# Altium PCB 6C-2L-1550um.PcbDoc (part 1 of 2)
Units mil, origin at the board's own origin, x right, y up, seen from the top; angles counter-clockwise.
Board outline 3937.01 x 2952.76 mil, 2 copper layers (Top Layer, Bottom Layer), stack 62.442 mil thick; 172 components, 97 nets, 523 pads, 239 vias.
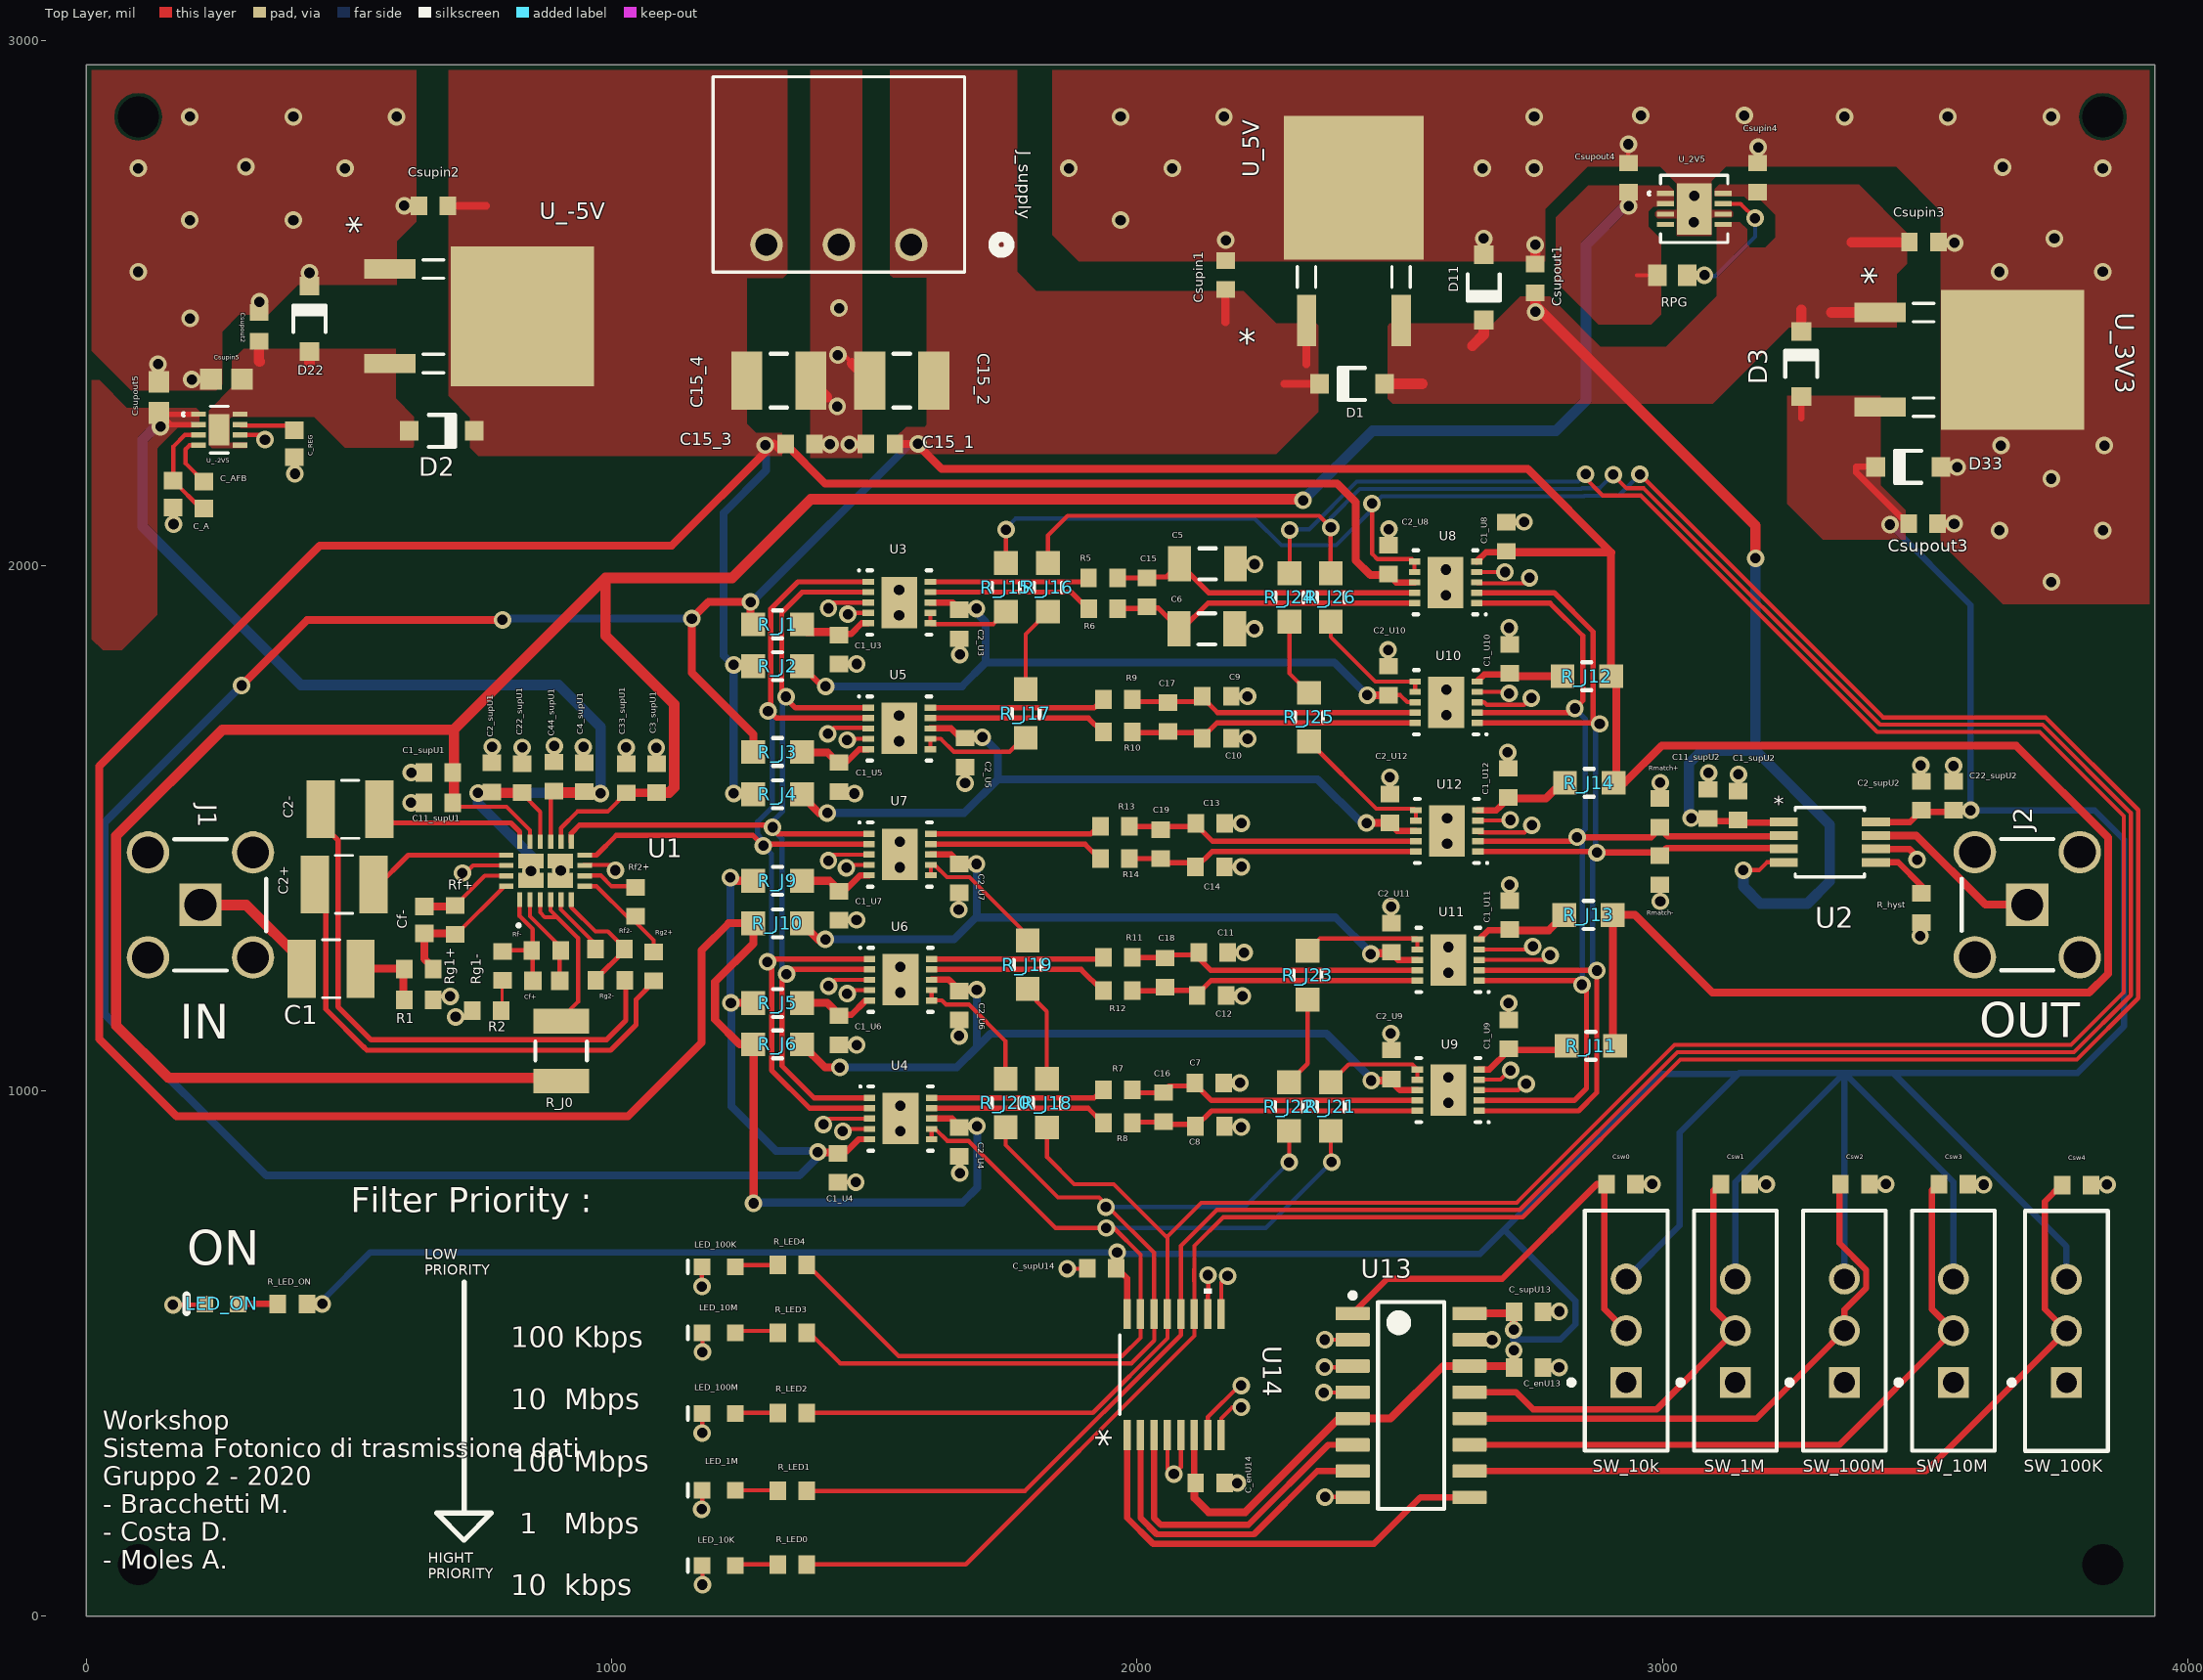
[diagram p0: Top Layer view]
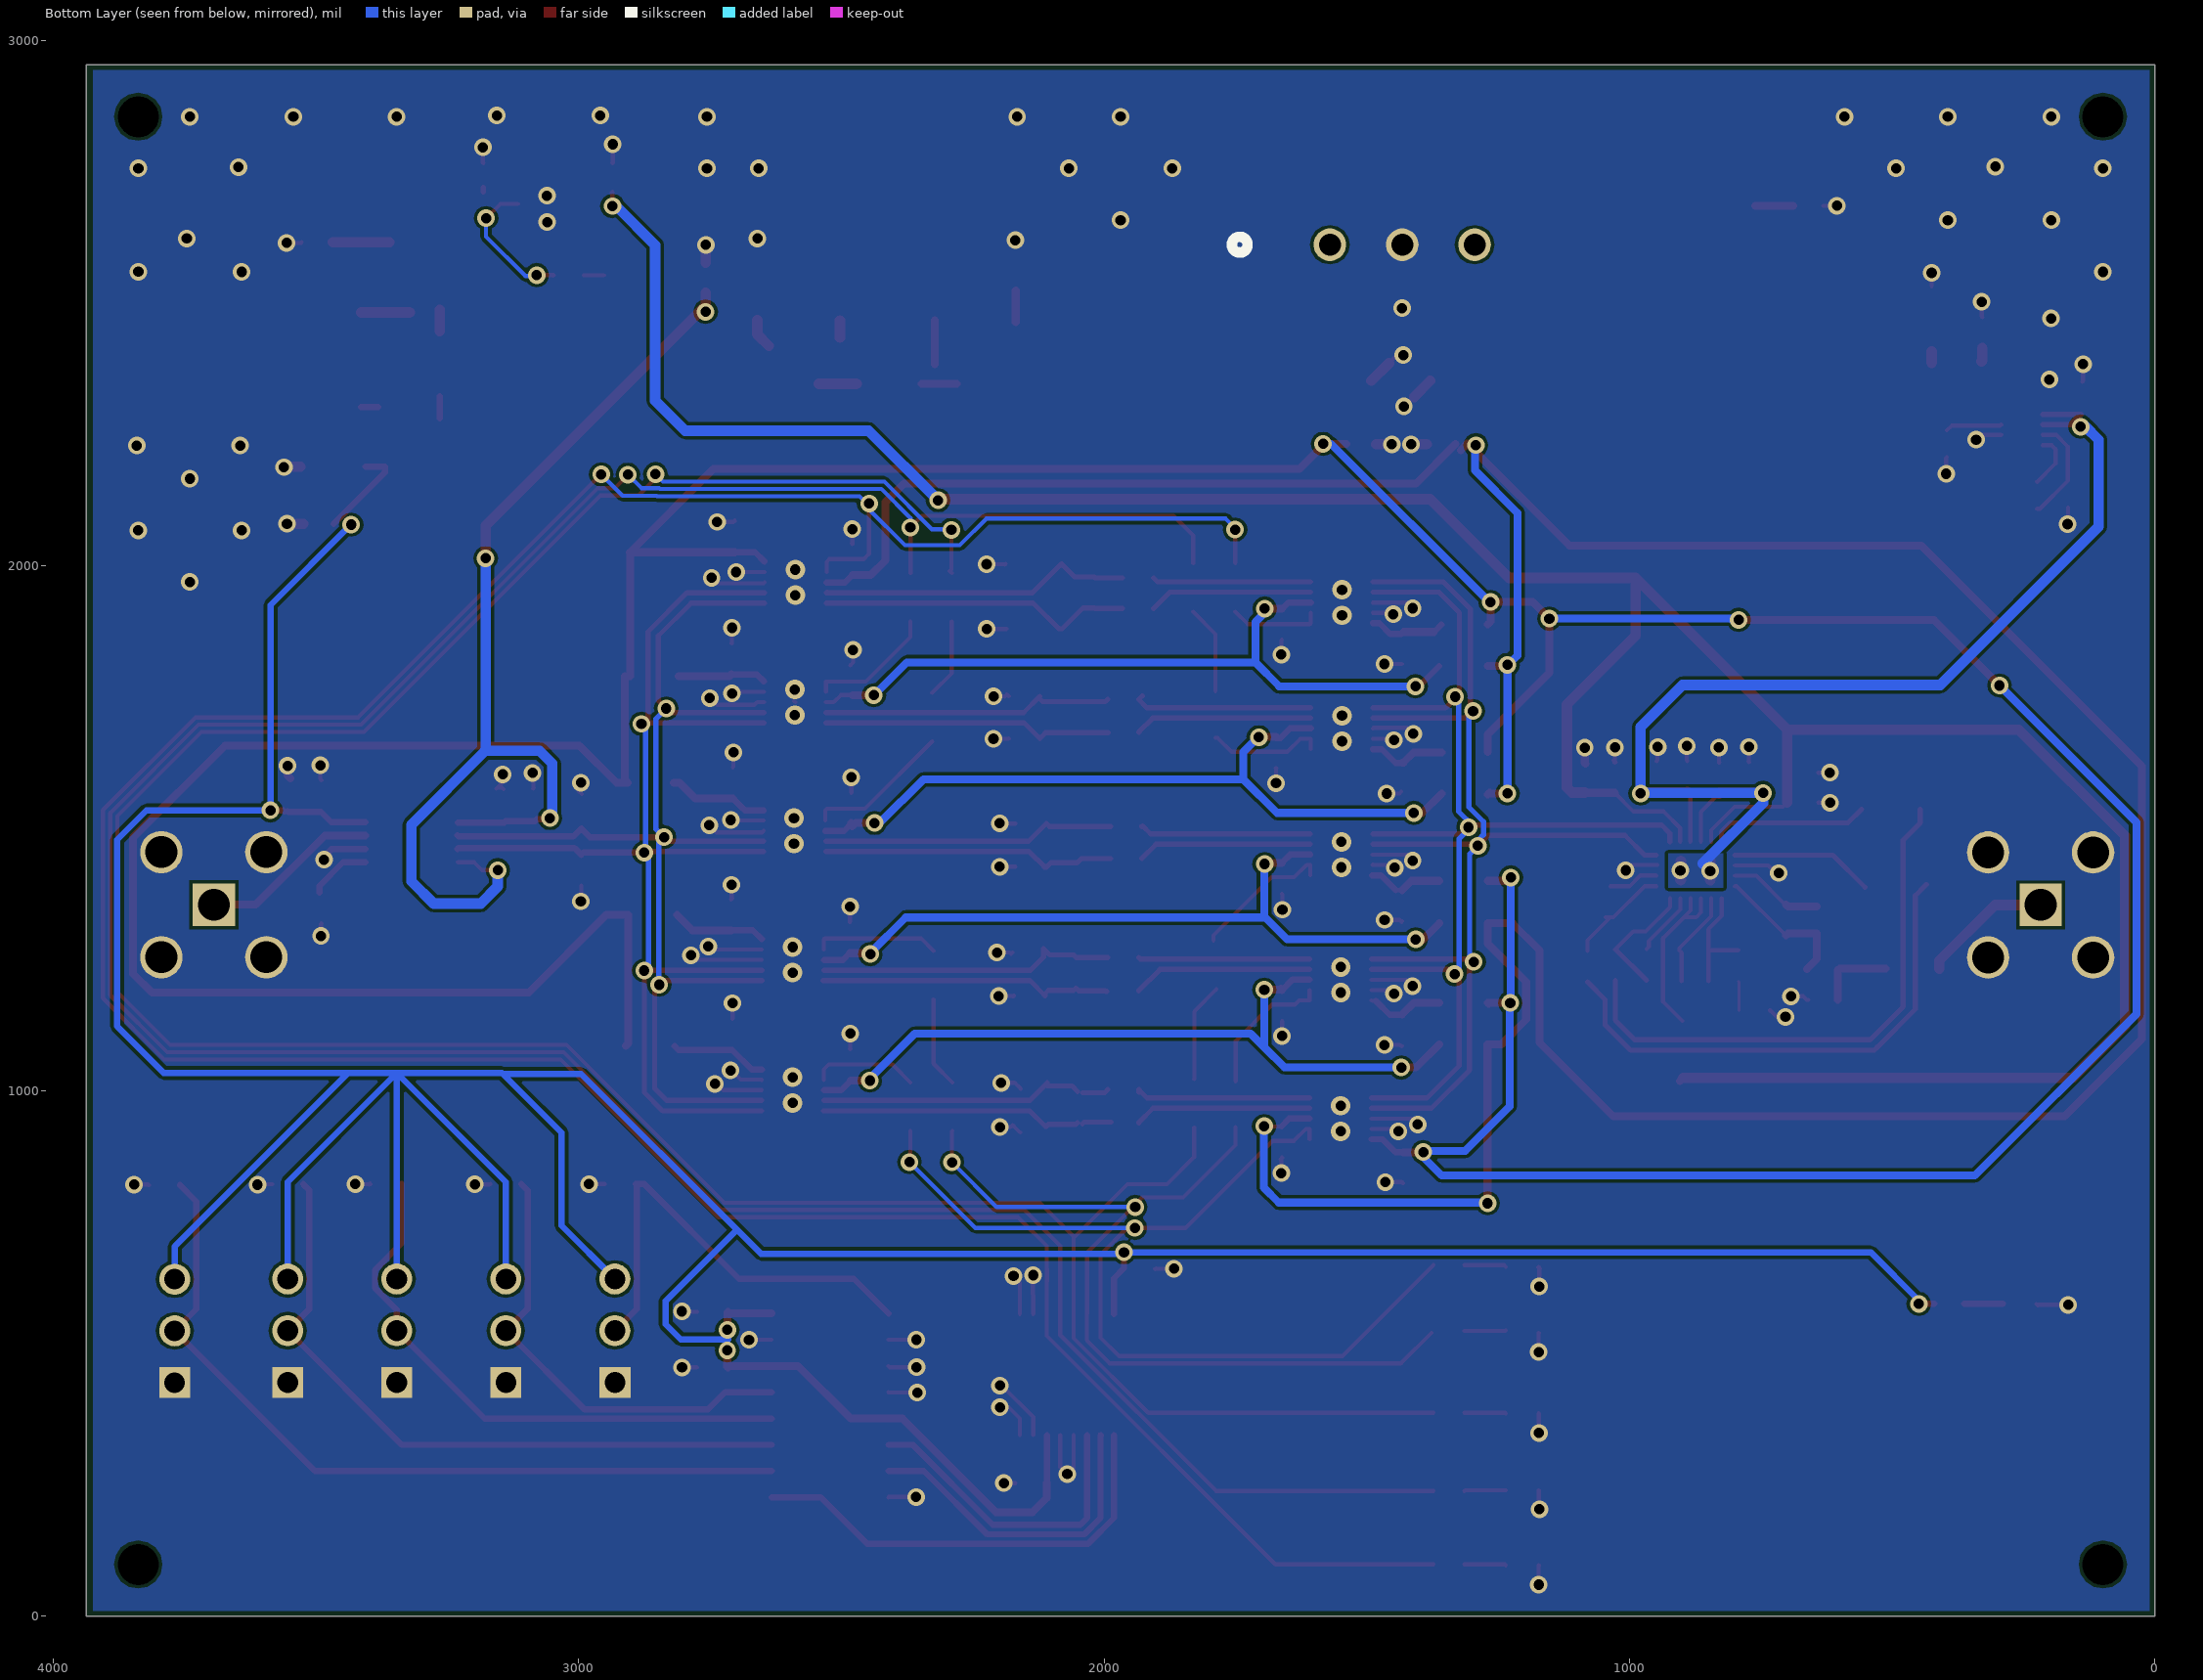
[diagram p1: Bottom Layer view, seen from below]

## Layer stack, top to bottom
Top Solder: solder mask 0.4, Solder Resist, Dk 3.5
Top Layer: signal copper 0.709
Dielectric1: core 61.024, FR-4, Dk 4.8
Bottom Layer: signal copper 0.709
Bottom Solder: solder mask 0.4, Solder Resist, Dk 3.5

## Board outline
3937.01,2952.76 0,2952.76 0,0 3937.01,0

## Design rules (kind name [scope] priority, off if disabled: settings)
BoardOutlineClearance [All] p1: gap=9.84 ignorepadtopadclearanceinfootprint=FALSE except(0: Arc-SplitContinuation Track-SplitContinuation SMDPad-SplitContinuation THPad-SplitContinuation Via-SplitContinuation Fill-SplitContinuation Poly-SplitContinuation Region-SplitContinuation Text-SplitContinuation)
Clearance Clearance-xPP-xTP-xTT [All] p1: gap=5.91 ignorepadtopadclearanceinfootprint=FALSE except(0: Arc-Hole Track-Hole SMDPad-Hole THPad-Hole Via-Hole Fill-Hole Poly-Hole Region-Hole Text-Hole)
ComponentClearance [All] p1: gap=9.84 collisioncheckmode=3 verticalgap=9.84 showdistances=FALSE
DiffPairsRouting [All] p1: maxlimit=9.84 minlimit=9.84 mostfreqgap=9.84 toplayer_minwidth=9.84 toplayer_maxwidth=15 toplayer_prefwidth=9.84 bottomlayer_minwidth=9.84 bottomlayer_maxwidth=15 bottomlayer_prefwidth=9.84 maxuncoupledlength=492.13
Height [All] p1: minheight=0 maxheight=984.25 prefheight=492.13
HoleSize HoleSize-PTH [All] p1: absolutevalues=TRUE maxlimit=78.74 minlimit=9.84 maxpercent=80.000 minpercent=20.000
HoleToHoleClearance [All] p1: gap=13.78 allowstackedmicrovias=TRUE
MinimumAnnularRing "Minimum IAR  >0.45mm" [((ObjectKind = 'Pad') OR (ObjectKind = 'Via')) And (Layer = 'MultiLayer') And (HoleDiameter > AsMM(0.45))] p1: minimumring=6.89 // minimum inner annular ring for pads > 0.45mm finished hole size
MinimumAnnularRing "Minimum IAR <=0.45mm" [((ObjectKind = 'Pad') OR (ObjectKind = 'Via')) And (Layer = 'MultiLayer') And (HoleDiameter <= AsMM(0.45))] p2: minimumring=6.89 // minimum inner annular ring for pads <= 0.45mm finished hole size
MinimumSolderMaskSliver [All] p1: minsoldermaskwidth=3.15
PlaneClearance PlaneClearance-IPI [All] p1: clearance=9.84
PlaneConnect [All] p1: planeconnectstyle=Direct reliefexpansion=6.89 reliefentries=4 reliefconductorwidth=7.87 reliefairgap=7.87
PolygonConnect PolygonConnect-xTW [All] p1: connectstyle=Direct reliefconductorwidth=7.87 reliefentries=4 polygonreliefangle="90 Angle" airgapwidth=7.87
RoutingCorners [All] p1: cornerstyle=45-Degree minsetback=98.43 maxsetback=98.43
RoutingVias "RoutingVias > 0.45mm" [(ObjectKind = 'Via') And (HoleDiameter > AsMM(0.45))] p1: holewidth=19.68 width=33.46 viastyle="Through Hole" minholewidth=19.68 minwidth=33.46 maxholewidth=35.43 maxwidth=49.21 // finishet hole size > 0.45mm
RoutingVias "RoutingVias <= 0.45mm" [(ObjectKind = 'Via') And (HoleDiameter <= AsMM(0.45))] p2: holewidth=11.81 width=25.59 viastyle="Through Hole" minholewidth=9.84 minwidth=23.62 maxholewidth=17.72 maxwidth=31.5 // finishet hole size <= 0.45mm
SilkToSilkClearance [All] p1: silktosilkclearance=7.87
SilkToSolderMaskClearance SilkscreenOverComponentPads [IsPad] p1: minsilkscreentomaskgap=7.87 clearancetoexposedcopper=TRUE
SolderMaskExpansion [All] p1: expansion=0 istentingtop=FALSE
UnRoutedNet [All] p1: checkbadconnections=TRUE
UnpouredPolygon [All] p1: allowunpoured=TRUE allowshelved=TRUE
Width Width-xTW [All] p1: maxlimit=59.06 minlimit=5.91 preferedwidth=7.87
17 further rules are at their usual default settings.

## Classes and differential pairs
component class SWITCH_stage: C1_U3 C1_U4 C1_U5 C1_U6 C1_U7 C1_U8 C1_U9 C1_U10 C1_U11 C1_U12 C2_U3 C2_U4 C2_U5 C2_U6 C2_U7 C2_U8 C2_U9 C2_U10 C2_U11 C2_U12 R_J1 R_J2 R_J3 R_J4 R_J5 R_J6 R_J9 R_J10 R_J11 R_J12 R_J13 R_J14 R_J15 R_J16 R_J17 R_J18 R_J19 R_J20 R_J21 R_J22 R_J23 R_J24 R_J25 R_J26 Rmatch+ Rmatch- U3 U4 U5 U6 U7 U8 U9 U10 U11 U12
net class 3.3V: 3V3
net class -15V: -15V
net class -5V: -5V
net class +15V: +15V
net class +5V: +5V
component class SUPPLY_15V: C15_1 C15_2 C15_3 C15_4 J_supply
component class SUPPLY_5V: C_A C_AFB C_REG Csupin1 Csupin2 Csupin4 Csupin5 Csupout1 Csupout2 Csupout4 Csupout5 D1 D2 D11 D22 RPG U_2V5 U_5V U_-2V5 U_-5V
component class SUPPLY_3V3: Csupin3 Csupout3 D3 D33 U_3V3
component class "STAGE _1_2": C1 C1_supU1 C2+ C2- C2_supU1 C3_supU1 C4_supU1 C11_supU1 C22_supU1 C33_supU1 C44_supU1 Cf+ Cf- J1 R1 R2 R_J0 Rf2+ Rf2- Rf+ Rf- Rg1+ Rg1- Rg2+ Rg2- U1
component class OUT_STAGE: C1_supU2 C2_supU2 C11_supU2 C22_supU2 J2 R_hyst U2
component class Selector_stage: C_enU13 C_enU14 C_supU13 C_supU14 Csw0 Csw1 Csw2 Csw3 Csw4 LED_1M LED_10K LED_10M LED_100K LED_100M LED_ON R_LED0 R_LED1 R_LED2 R_LED3 R_LED4 R_LED_ON SW_1M SW_10k SW_10M SW_100K SW_100M U13 U14
component class Filters: C5 C6 C7 C8 C9 C10 C11 C12 C13 C14 C15 C16 C17 C18 C19 R5 R6 R7 R8 R9 R10 R11 R12 R13 R14
differential pair Diff_Pair9: +Diff_Pair9_P -Diff_Pair9_N
differential pair Diff_pair00: +Diff_pair00_P -Diff_pair00_N
differential pair Diff_pair0: +Diff_pair0_P -Diff_pair0_N
differential pair Diff_pair61: +Diff_pair61_P -Diff_pair61_N
differential pair Diff_pair51: +Diff_pair51_P -Diff_pair51_N
differential pair Diff_pair41: +Diff_pair41_P -Diff_pair41_N
differential pair Diff_pair31: +Diff_pair31_P -Diff_pair31_N
differential pair Diff_pair21: +Diff_pair21_P -Diff_pair21_N
differential pair Diff_pair6: +Diff_pair6_P -Diff_pair6_N
differential pair Diff_pair5: +Diff_pair5_P -Diff_pair5_N
differential pair Diff_pair4: +Diff_pair4_P -Diff_pair4_N
differential pair Diff_pair3: +Diff_pair3_P -Diff_pair3_N
differential pair Diff_pair2: +Diff_pair2_P -Diff_pair2_N
differential pair Diff_pair1: +Diff_pair1_P -Diff_pair1_N

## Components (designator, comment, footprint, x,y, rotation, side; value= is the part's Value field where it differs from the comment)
C1 "JMK325ABJ337MM-PE" CAPC3225X280N 465.8,1232.54 r0 top
C1_supU1 "06031C104KAT2A" 1608[0603] 669.72,1605.77 r180 top value=100nF
C1_supU2 "06031C104KAT2A" 1608[0603] 3143.85,1543.41 r270 top value=100nF
C1_U3 "06031C104KAT2A" 1608[0603] 1432.77,1840.09 r90 top value=100nF
C1_U4 "06031C104KAT2A" 1608[0603] 1430.8,853.63 r90 top value=100nF
C1_U5 "06031C104KAT2A" 1608[0603] 1432.62,1597.42 r90 top value=100nF
C1_U6 "06031C104KAT2A" 1608[0603] 1432.77,1115.43 r90 top value=100nF
C1_U7 "06031C104KAT2A" 1608[0603] 1432.62,1352.63 r90 top value=100nF
C1_U8 "06031C104KAT2A" 1608[0603] 2703.02,2054.6 r270 top value=100nF
C1_U9 "06031C104KAT2A" 1608[0603] 2707.71,1107.55 r270 top value=100nF
C1_U10 "06031C104KAT2A" 1608[0603] 2709.06,1822.29 r270 top value=100nF
C1_U11 "06031C104KAT2A" 1608[0603] 2709.68,1334.9 r270 top value=100nF
C1_U12 "06031C104KAT2A" 1608[0603] 2706.6,1586.35 r270 top value=100nF
C2+ "JMK325ABJ337MM-PE" CAPC3225X280N 490.39,1392.88 r180 top
C2- "JMK325ABJ337MM-PE" CAPC3225X280N 501.98,1536.13 r180 top
C2_supU1 "06031C104KAT2A" 1608[0603] 772.03,1596.66 r90 top value=100nF
C2_supU2 "06031C104KAT2A" 1608[0603] 3493.12,1561.63 r270 top value=100nF
C2_U3 "06031C104KAT2A" 1608[0603] 1661.12,1888.09 r90 top value=100nF
C2_U4 "06031C104KAT2A" 1608[0603] 1661.53,902.64 r90 top value=100nF
C2_U5 "06031C104KAT2A" 1608[0603] 1672.21,1644.07 r90 top value=100nF
C2_U6 "06031C104KAT2A" 1608[0603] 1661.12,1162.42 r90 top value=100nF
C2_U7 "06031C104KAT2A" 1608[0603] 1661.31,1404.61 r90 top value=100nF
C2_U8 "06031C104KAT2A" 1608[0603] 2478.86,2011.42 r270 top value=100nF
C2_U9 "06031C104KAT2A" 1608[0603] 2483.71,1050.25 r270 top value=100nF
C2_U10 "06031C104KAT2A" 1608[0603] 2478.86,1780.9 r270 top value=100nF
C2_U11 "06031C104KAT2A" 1608[0603] 2484.11,1291.45 r270 top value=100nF
C2_U12 "06031C104KAT2A" 1608[0603] 2481.44,1537.77 r270 top value=100nF
C3_supU1 "06031C104KAT2A" 1608[0603] 1084.96,1595.27 r90 top value=100nF
C4_supU1 "06031C104KAT2A" 1608[0603] 947.34,1597.4 r90 top value=100nF
C5 "12063C155KAT2A" C1206 2134.03,2003.25 r180 top value=1.5uF
C6 "12063C155KAT2A" C1206 2132.82,1879.48 r180 top value=1.5uF
C7 "0603YD154KAT2A" 1608[0603] 2137.62,1015.32 r180 top value=150nF
C8 "0603YD154KAT2A" 1608[0603] 2138.78,932.58 r180 top value=150nF
C9 "06033C153M4T2A" 1608[0603] 2151.74,1751.11 r180 top value=15nF
C10 "06033C153M4T2A" 1608[0603] 2151.74,1670.74 r180 top value=15nF
C11 "06031C152JAT2A" 1608[0603] 2144.86,1263.35 r180 top value=1.5nF
C11_supU1 "06035C102KAT4A" 1608[0603] 669.72,1548.68 r180 top value=1nF
C11_supU2 "06033D225KAT2A" 1608[0603] 3086.75,1546.27 r270 top value=2.2uF
C12 "06031C152JAT2A" 1608[0603] 2141.79,1181.2 r180 top value=1.5nF
C13 "06031A820F4T2A" 1608[0603] 2139.08,1508.98 r180 top value=82pF
C14 "06031A820F4T2A" 1608[0603] 2138.78,1426.06 r180 top value=82pF
C15 "0603YD684KAT2A" 1608[0603] 2018.64,1948.7 r90 top value=0.68uF
C15_1 "06033G104ZAT2A" 1608[0603] 1511.37,2231.11 r0 top value=0.1uF
C15_2 "12103G106ZAT2A" C1210_M 1552.14,2351.82 r0 top value=10uF
C15_3 "06033G104ZAT2A" 1608[0603] 1358.29,2231.11 r0 top value=0.1uF
C15_4 "12103G106ZAT2A" C1210_M 1317.87,2351.82 r0 top value=10uF
C16 "06033D683MAT2A" 1608[0603] 2050.31,969.2 r90 top value=68nF
C17 "06031C682JAT2A" 1608[0603] 2058.86,1711.33 r90 top value=6.8nF
C18 "06031C681JAT2A" 1608[0603] 2053.4,1225.2 r90 top value=680pF
C19 "06031A330FAT2A" 1608[0603] 2045.23,1469.53 r90 top value=33pF
C22_supU1 "06035C102KAT4A" 1608[0603] 829.12,1595.27 r90 top value=1nF
C22_supU2 "06033D225KAT2A" 1608[0603] 3554.09,1561.63 r270 top value=2.2uF
C33_supU1 "06035C102KAT4A" 1608[0603] 1027.86,1594.95 r90 top value=1nF
C44_supU1 "06035C102KAT4A" 1608[0603] 890.02,1598.38 r90 top value=1nF
C_A "0603ZD105KAT2A" CAPC1608X86X35LL15T15 164.69,2136.15 r90 top
C_AFB "06035C-103KAT2A" CAPC1608X90X35LL15T15 223.76,2133.77 r270 top
C_enU13 "06031C104KAT2A" 1608[0603] 2745.31,473.57 r0 top value=100nF
C_enU14 "06031C104KAT2A" 1608[0603] 2138.91,253.37 r0 top value=100nF
C_REG "0603ZD105KAT2A" CAPC1608X86X35LL15T15 395.37,2231.68 r90 top
C_supU13 "06031C104KAT2A" 1608[0603] 2745.13,579.2 r0 top value=100nF
C_supU14 "06031C104KAT2A" 1608[0603] 1932.46,662.45 r180 top value=100nF
Cf+ "06031A1R0BAT2A" CAPC1608X90X35LL15T15 874.96,1209.13 r0 top
Cf- "06031A1R0BAT2A" CAPC1608X90X35LL15T15 643.3,1325.26 r90 top
Csupin1 "0603YC334JAT2A" 1608[0603] 2168.18,2553.14 r270 top value=330nF
Csupin2 "06033D225KAT2A" 1608[0603] 660.17,2684.58 r0 top value=2.2uF
Csupin3 "06033D105KAT2A" 1608[0603] 3497.83,2615.42 r180 top value=1uF
Csupin4 "06033D105KAT2A" 1608[0603] 3181.39,2738.53 r270 top value=1uF
Csupin5 "0603ZD475KAT2A" CAPC1608X90X35NL15T15 266.6,2354.83 r0 top
Csupout1 "06031C104JAT2A" 1608[0603] 2758,2546.71 r270 top value=0.1uF
Csupout2 "06033D105KAT2A" 1608[0603] 328.31,2454.08 r90 top value=1uF
Csupout3 "06033D225KAT2A" 1608[0603] 3496.39,2079.3 r180 top value=2.2uF
Csupout4 "06033D105KAT2A" 1608[0603] 2935.8,2738.53 r270 top value=1uF
Csupout5 "0603ZD475KAT2A" CAPC1608X90X35NL15T15 137.71,2320.09 r270 top
Csw0 "06031C104KAT2A" 1608[0603] 2920.82,822.39 r180 top value=100nF
Csw1 "06031C104KAT2A" 1608[0603] 3138.72,822.39 r180 top value=100nF
Csw2 "06031C104KAT2A" 1608[0603] 3366.49,822.39 r180 top value=100nF
Csw3 "06031C104KAT2A" 1608[0603] 3554.09,822.39 r180 top value=100nF
Csw4 "06031C104KAT2A" 1608[0603] 3788.68,820.68 r180 top value=100nF
D1 "1N4148W-7-F" DIOD-SOD123-2_V 2409.09,2345.71 r180 top
D2 "1N4148W-7-F" DIOD-SOD123-2_V 676.44,2256.2 r0 top
D3 "1N4148W-7-F" DIOD-SOD123-2_V 3264.48,2383.79 r90 top
D11 "1N4148W-7-F" DIOD-SOD123-2_V 2659.96,2529.34 r270 top
D22 "1N4148W-7-F" DIOD-SOD123-2_V 424.46,2469.6 r90 top
D33 "1N4148W-7-F" DIOD-SOD123-2_V 3467.98,2187.98 r180 top
J1 "731000114" MOLX-731000114_V 216.97,1353.89 r0 top
J2 "731000114" MOLX-731000114_V 3694.6,1354.39 r180 top
J_supply "8971054" CONN_8971054_RSP 1570,2610.69 r180 top locked
LED_1M "150060YS75000" 0603_A 1203.67,239.91 r0 top
LED_10K "150060YS75000" 0603_A 1203.66,96.69 r0 top (schematic designator LED_10k)
LED_10M "150060YS75000" 0603_A 1203.66,539.28 r0 top
LED_100K "150060YS75000" 0603_A 1203.66,665.08 r0 top
LED_100M "150060YS75000" 0603_A 1203.66,386.17 r0 top
LED_ON "598-8070-107F" DIAL-0603-2_V 257.03,594.41 r0 top
R1 "ERJ-PA3F1150V" 1608[0603] 632.54,1173.18 r180 top value=115
R2 "ERJ-3EKF34R8V" 1608[0603] 761.87,1153.11 r180 top value=34.8
R5 "ERJ-PA3J6R2V" 1608[0603] 1935.13,1976.3 r180 top value=6.2
R6 "ERJ-PA3J6R2V" 1608[0603] 1935.42,1918.11 r180 top value=6.2
R7 "ERJ-PA3J6R2V" 1608[0603] 1963.39,1002.36 r180 top value=6.2
R8 "ERJ-PA3J6R2V" 1608[0603] 1963.39,939.15 r180 top value=6.2
R9 "ERJ-PA3J6R2V" 1608[0603] 1963.39,1745.12 r180 top value=6.2
R10 "ERJ-PA3J6R2V" 1608[0603] 1963.39,1682.91 r180 top value=6.2
R11 "ERJ-PA3J6R2V" 1608[0603] 1963.43,1253.88 r180 top value=6.2
R12 "ERJ-PA3J6R2V" 1608[0603] 1963.43,1190.67 r180 top value=6.2
R13 "ERJ-PA3J6R2V" 1608[0603] 1957.73,1503.24 r180 top value=6.2
R14 "ERJ-PA3J6R2V" 1608[0603] 1957.73,1442.24 r180 top value=6.2
R_hyst "ERJ-UP3f4753V" 1608[0603] 3493.11,1348.17 r270 top value=475k
R_J0 "CRCW12100000Z0EA" RESC3225X60X45NL20T20 903.45,1075.84 r90 top
R_J1 "CR0805-J/-000ELF" FP-CR0805-MFG 1315.64,1887.84 r0 top
R_J2 "CR0805-J/-000ELF" FP-CR0805-MFG 1315.64,1808.46 r0 top
R_J3 "CR0805-J/-000ELF" FP-CR0805-MFG 1315.64,1645.04 r0 top
R_J4 "CR0805-J/-000ELF" FP-CR0805-MFG 1315.64,1564.46 r0 top
R_J5 "CR0805-J/-000ELF" FP-CR0805-MFG 1315.64,1167.33 r0 top
R_J6 "CR0805-J/-000ELF" FP-CR0805-MFG 1315.64,1088.58 r0 top
R_J9 "CR0805-J/-000ELF" FP-CR0805-MFG 1315.64,1399.83 r0 top
R_J10 "CR0805-J/-000ELF" FP-CR0805-MFG 1315.64,1318.95 r0 top
R_J11 "CR0805-J/-000ELF" FP-CR0805-MFG 2863.95,1085.56 r0 top
R_J12 "CR0805-J/-000ELF" FP-CR0805-MFG 2855.97,1789.19 r0 top
R_J13 "CR0805-J/-000ELF" FP-CR0805-MFG 2859.26,1334.9 r0 top
R_J14 "CR0805-J/-000ELF" FP-CR0805-MFG 2860.69,1586.35 r0 top
R_J15 "CR0805-J/-000ELF" FP-CR0805-MFG 1750.14,1958.47 r270 top
R_J16 "CR0805-J/-000ELF" FP-CR0805-MFG 1830.41,1958.28 r270 top
R_J17 "CR0805-J/-000ELF" FP-CR0805-MFG 1787.87,1718.19 r270 top
R_J18 "CR0805-J/-000ELF" FP-CR0805-MFG 1828.37,976.66 r270 top
R_J19 "CR0805-J/-000ELF" FP-CR0805-MFG 1791.58,1240.18 r270 top
R_J20 "CR0805-J/-000ELF" FP-CR0805-MFG 1749.62,976.83 r270 top
R_J21 "CR0805-J/-000ELF" FP-CR0805-MFG 2368.63,969.87 r270 top
R_J22 "CR0805-J/-000ELF" FP-CR0805-MFG 2288.88,969.87 r270 top
R_J23 "CR0805-J/-000ELF" FP-CR0805-MFG 2324.59,1220.2 r270 top
R_J24 "CR0805-J/-000ELF" FP-CR0805-MFG 2289.88,1939.25 r270 top
R_J25 "CR0805-J/-000ELF" FP-CR0805-MFG 2327.31,1711.33 r270 top
R_J26 "CR0805-J/-000ELF" FP-CR0805-MFG 2368.63,1939.25 r270 top
R_LED0 "ERJ-PA3F1300V" 1608[0603] 1343.3,98.6 r0 top value=130
R_LED1 "ERJ-PA3F1300V" 1608[0603] 1343.3,238.45 r0 top value=130
R_LED2 "ERJ-PA3F1300V" 1608[0603] 1343.3,387.12 r0 top value=130
R_LED3 "ERJ-PA3F1300V" 1608[0603] 1343.3,539.28 r0 top value=130
R_LED4 "ERJ-PA3F1300V" 1608[0603] 1343.3,668.32 r0 top value=130
R_LED_ON "ERJ-PA3F1300V" 1608[0603] 391.9,594.41 r0 top value=130
Rf2+ "ERJ-PA3F2491V" 1608[0603] 1045.16,1359.87 r270 top value=2.49k
Rf2- "ERJ-PA3F2491V" 1608[0603] 996.6,1269.61 r0 top value=2.49k
Rf+ "ERJ-P03D3480V" 1608[0603] 701.67,1325.26 r270 top value=348
Rf- "ERJ-P03D3480V" 1608[0603] 875.03,1267.21 r180 top value=348
Rg1+ "ERJ-PA3F49R9V" 1608[0603] 632.54,1232.23 r180 top value=49.9
Rg1- "ERJ-PA3F49R9V" 1608[0603] 792.35,1238.09 r90 top value=49.9
Rg2+ "ERJ-PA3F24R9V" 1608[0603] 1079.74,1236.82 r270 top value=24.9
Rg2- "ERJ-PA3F24R9V" 1608[0603] 996.95,1210.46 r0 top value=24.9
Rmatch+ "ERJ-PA3F12R0V" 1608[0603] 2994.96,1528.99 r270 top value=12
Rmatch- "ERJ-PA3F12R0V" 1608[0603] 2995.1,1419.9 r90 top value=12
RPG "ERJ-3EKF1003V" RESC1608X55X30ML15T15 3018.92,2552.49 r180 top
SW_1M "EG1218" ESWI-EG1218_V 3138.72,543.46 r90 top
SW_10k "EG1218" ESWI-EG1218_V 2931.03,543.46 r90 top
SW_10M "EG1218" ESWI-EG1218_V 3554.09,543.46 r90 top
SW_100K "EG1218" ESWI-EG1218_V 3769.21,543.16 r90 top
SW_100M "EG1218" ESWI-EG1218_V 3346.41,543.46 r90 top
U1 "LTC6419IV#PBF" LTC6419IVPBF 873.79,1419.22 r90 top
U2 "LTC6752HMS8-2#PBF" MSOP-8_MS_LIT 3318.64,1473.36 r0 top
U3 "ADG1421BCPZ-REEL7" ADI-CP-10-9_V 1547.34,1929.6 r0 top
U4 "ADG1421BCPZ-REEL7" ADI-CP-10-9_V 1549.91,947.27 r0 top
U5 "ADG1421BCPZ-REEL7" ADI-CP-10-9_V 1547.34,1689.8 r0 top
U6 "ADG1421BCPZ-REEL7" ADI-CP-10-9_V 1549.64,1211.43 r0 top
U7 "ADG1421BCPZ-REEL7" ADI-CP-10-9_V 1548.38,1449.77 r0 top
U8 "ADG1421BCPZ-REEL7" ADI-CP-10-9_V 2587.14,1967.91 r180 top
U9 "ADG1421BCPZ-REEL7" ADI-CP-10-9_V 2592.39,1001.48 r180 top
U10 "ADG1421BCPZ-REEL7" ADI-CP-10-9_V 2588.19,1739.76 r180 top
U11 "ADG1421BCPZ-REEL7" ADI-CP-10-9_V 2592.39,1249.33 r180 top
U12 "ADG1421BCPZ-REEL7" ADI-CP-10-9_V 2589.72,1494.85 r180 top
U13 "CD4532BM" D0016A_M 2521.58,401.22 r0 top
U14 "74VHC238FT" TSSOP16B 2070.58,459.97 r90 top
U_2V5 "ADP7104ACPZ-2.5-R7" CP_8_5_ADI 3060.63,2678.71 r0 top
U_3V3 "TPS7B8833QKVURQ1" KVU3_TEX 3666.56,2391.6 r270 top
U_5V "UA78M05IKVURG3" KVU3_TEX 2412.56,2719 r0 top
U_-2V5 "ADP7185ACPZN2.5-R7" CP_8_27_ADI 252.46,2258.45 r0 top
U_-5V "UA79M05CKVURG3" KVU3_TEX 829.77,2474.51 r270 top

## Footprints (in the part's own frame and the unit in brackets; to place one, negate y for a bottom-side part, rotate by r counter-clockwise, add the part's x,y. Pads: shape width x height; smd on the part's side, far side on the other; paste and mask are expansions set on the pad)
0603_A [mm] "Chip LED, 2-Leads, Body 1.6x0.8mm, IPC Medium Density"
  rect 0.8x0.8 smd: 1(-0.8,0) 2(0.8,0)
  silkscreen extent -1.5,-0.3 -1.5,0.3, body extent -0.8,-0.4 0.8,0.4, height 0.7
1608[0603] [mm] "Chip Capacitor, Body 1.6x0.8mm, IPC High Density"
  rect 0.8x0.9 smd: 1(-0.7,0) 2(0.7,0)
  body extent -0.87,-0.48 0.87,0.48, height 1.3
ADI-CP-10-9_V [mm] "SON, 10-Leads, Body 3x3mm, Pitch 0.5mm, Thermal Pad 2.48x1.74mm"
  rect 0.55x0.3 smd: 1(-1.5,1) 2(-1.5,0.5) 3(-1.5,0) 4(-1.5,-0.5) 5(-1.5,-1) 6(1.5,-1) 7(1.5,-0.5) 8(1.5,0) 9(1.5,0.5) 10(1.5,1)
  rect 1.74x2.48 smd: 11(0,0)
  silkscreen extent -2,-1.55 1.55,1.6, body extent -1.5,-1.5 1.5,1.5, height 0.85
C1206 [mm] "Chip Capacitor, Body 3.2x1.6mm, IPC High Density"
  rect 1.1x1.7 smd: 1(-1.35,0) 2(1.35,0)
  silkscreen extent -0.4,-0.75 0.4,0.75, body extent -1.7,-0.9 1.7,0.9, height 1.3
C1210_M [mm] "Chip Capacitor, Body 3.2x2.5mm, IPC Low Density"
  rect 1.5x2.8 smd: 1(-1.55,0) 2(1.55,0)
  silkscreen extent -0.4,-1.3 0.4,1.3, body extent -1.7,-1.35 1.7,1.35, height 1.5
CAPC1608X86X35LL15T15 [mm] "Chip Capacitor, 2-Leads, Body 1.75x0.96mm, IPC High Density"
  rect 0.85x0.9 smd: 1(-0.65,0) 2(0.65,0)
  body extent -0.87,-0.48 0.87,0.48, height 0.86
CAPC1608X90X35LL15T15 [mm] "Chip Capacitor, 2-Leads, Body 1.60x0.81mm, IPC High Density"
  rect 0.85x0.9 smd: 1(-0.65,0) 2(0.65,0)
  body extent -0.88,-0.48 0.87,0.48, height 0.9
CAPC1608X90X35NL15T15 [mm] "Chip Capacitor, 2-Leads, Body 1.60x0.81mm, IPC Medium Density"
  rect 1.05x1 smd: 1(-0.75,0) 2(0.75,0)
  body extent -0.88,-0.48 0.87,0.48, height 0.9
CAPC3225X280N [mm]
  rect 1.37x2.81 smd: 1(-1.42,0) 2(1.42,0)
  silkscreen extent -0.42,-1.4 0.42,1.4
CONN_8971054_RSP [mil]
  round 62 hole 42 mask+0: 1(0,0) 2(137.79,0) 3(275.59,0)
  silkscreen extent -187,-320 377,52, body extent 0,0 10,10, height 10
CP_8_5_ADI [mil]
  rect 32x10 smd paste+0 mask+0: 1(-55,29.53) 2(-55,9.84) 3(-55,-9.84) 4(-55,-29.53) 5(55,-29.53) 6(55,-9.84) 7(55,9.84) 8(55,29.53)
  rect 66x98 smd paste+0 mask+0: 9(0,0)
  silkscreen extent -88,-64 64,64, body extent -59,-59 59,59, height 31
CP_8_27_ADI [mm]
  rect 0.705x0.249 smd paste+0 mask+0: 1(-1.002,0.75) 2(-1.002,0.25) 3(-1.002,-0.25) 4(-1.002,-0.75) 5(1.002,-0.75) 6(1.002,-0.25) 7(1.002,0.25) 8(1.002,0.75)
  rect 1x1.5 smd paste+0 mask+0: 9(0,0)
  silkscreen extent -1.78,-1.13 0.43,1.13, body extent -1.05,-1 1.05,1, height 0.55
D0016A_M [mm] "SOIC, 16-Leads, Body 10x4mm, Pitch 1.27mm, IPC Low Density"
  rrect15% 1.65x0.65 smd: 1(-2.825,4.445) 2(-2.825,3.175) 3(-2.825,1.905) 4(-2.825,0.635) 5(-2.825,-0.635) 6(-2.825,-1.905) 7(-2.825,-3.175) 8(-2.825,-4.445) 9(2.825,-4.445) 10(2.825,-3.175) 11(2.825,-1.905) 12(2.825,-0.635) 13(2.825,0.635) 14(2.825,1.905) 15(2.825,3.175) 16(2.825,4.445)
  silkscreen extent -2.95,-5 1.6,5.44, body extent -3,-4.95 3,4.95, height 1.59
DIAL-0603-2_V [mm] "LED, 2-Leads, Body 1.6x0.8mm"
  rect 0.8x0.8 smd: 1(-0.8,0) 2(0.8,0)
  silkscreen extent -1.7,-0.4 -1.7,0.4, body extent -0.81,-0.39 0.81,0.39, height 0.71
DIOD-SOD123-2_V [mm] "SOD123, 2-Leads, Body 2.7x1.55mm, Height 1.45mm"
  rect 0.9x0.95 smd: 1(-1.575,0) 2(1.575,0)
  silkscreen extent -0.64,-0.83 0.64,0.77, body extent -1.35,-0.77 1.35,0.77, height 1.45
ESWI-EG1218_V [mm] "THD, 3-Leads, Body 11.6x4mm, Pitch 2.5mm"
  rect 1.5x1.5 hole 1: 1(-2.5,0)
  round 1.5 hole 1: 2(0,0) 3(2.5,0)
  silkscreen extent -5.8,-2 5.8,2.77, body extent -5.8,-2 5.8,2, height 7.4
FP-CR0805-MFG [mm]
  rect 1.15x1.15 smd paste+0 mask+0: 1(-1.175,0) 2(1.175,0)
  silkscreen extent -0.23,-0.67 0.23,0.67, body extent -1.85,-0.77 1.85,0.77, height 0.25
KVU3_TEX [mil]
  rect 37x98 smd paste+0 mask+0: 1(-90,-252.5) 3(90,-252.5)
  rect 266x273 smd paste+0 mask+0: 2(0,0)
  silkscreen extent -108,-189 107,-150, body extent 0,0 10,10, height 10
LTC6419IVPBF [mm]
  rect 0.7x0.25 smd: 1(-1.4,1.25) 2(-1.4,0.75) 3(-1.4,0.25) 4(-1.4,-0.25) 5(-1.4,-0.75) 6(-1.4,-1.25) 11(1.4,-1.25) 12(1.4,-0.75) 13(1.4,-0.25) 14(1.4,0.25) 15(1.4,0.75) 16(1.4,1.25)
  rect 0.25x0.7 smd: 7(-0.75,-1.9) 8(-0.25,-1.9) 9(0.25,-1.9) 10(0.75,-1.9) 17(0.75,1.9) 18(0.25,1.9) 19(-0.25,1.9) 20(-0.75,1.9)
  rect 0.725x1.225 smd: 21(-0.462,0.713) 22(0.463,0.713) 23(-0.462,-0.713) 24(0.463,-0.713)
  silkscreen extent -2.7,1.25 -2.6,1.35, body extent -1.5,-2 1.5,2, height 0.94
MOLX-731000114_V [mm] "Connector, 5-Leads, Body 14.8x6.35mm, Pitch 2.54mm"
  rect 2.05x2.05 hole 1.54: 1(0,0)
  round 2.05 hole 1.54: 2(-2.54,2.54) 3(-2.54,-2.54) 4(2.54,-2.54) 5(2.54,2.54)
  silkscreen extent -1.26,-3.17 3.17,3.18, body extent -11.62,-3.17 3.18,3.18, height 9.57
MSOP-8_MS_LIT [mil]
  rect 53.5x17 smd paste+0 mask+0: 1(-87.75,38.39) 2(-87.75,12.8) 3(-87.75,-12.79) 4(-87.75,-38.39) 5(87.75,-38.39) 6(87.75,-12.79) 7(87.75,12.8) 8(87.75,38.39)
  silkscreen extent -66,-66 66,66, body extent -101,-61 101,61, height 43
RESC1608X55X30ML15T15 [mm] "Chip Resistor, 2-Leads, Body 1.60x0.80mm, IPC Low Density"
  rect 0.9x1.05 smd: 1(-0.725,0) 2(0.725,0)
  body extent -0.87,-0.48 0.87,0.48, height 0.55
RESC3225X60X45NL20T20 [mm] "Chip Resistor, 2-Leads, Body 3.20x2.50mm, IPC Medium Density"
  rect 1.2x2.7 smd: 1(-1.45,0) 2(1.45,0)
  silkscreen extent -0.45,-1.25 0.45,1.25, body extent -1.7,-1.35 1.7,1.35, height 0.6
TSSOP16B [mil]
  rect 57.5x14 smd paste+0 mask+0: 1(-115.25,89.57) 2(-115.25,63.98) 3(-115.25,38.39) 4(-115.25,12.8) 5(-115.25,-12.8) 6(-115.25,-38.39) 7(-115.25,-63.98) 8(-115.25,-89.57) 9(115.25,-89.57) 10(115.25,-63.98) 11(115.25,-38.39) 12(115.25,-12.8) 13(115.25,12.8) 14(115.25,38.39) 15(115.25,63.98) 16(115.25,89.57)
  silkscreen extent -75,-71 164,104, body extent -130,-98 130,99, height 47

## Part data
C1 C2+ C2-: "330ÂµF Â±20% 6.3V Ceramic Capacitor X5R 1210 (3225 Metric)", Package="3225 Taiyo Yuden"
C1_supU1 C1_supU2 C1_U3 C1_U4 C1_U5 C1_U6 C1_U7 C1_U8 C1_U9 C1_U10 C1_U11 C1_U12 C2_supU1 C2_supU2 C2_U3 C2_U4 C2_U5 C2_U6 C2_U7 C2_U8 C2_U9 C2_U10 C2_U11 C2_U12 C3_supU1 C4_supU1 C5 C6 C7 C8 C9 C10 C11 C11_supU1 C11_supU2 C12 C13 C14 C15 C15_1 C15_2 C15_3 C15_4 C16 C17 C18 C19 C22_supU1 C22_supU2 C33_supU1 C44_supU1 C_enU13 C_enU14 C_supU13 C_supU14 Csupin1 Csupin2 Csupin3 Csupin4 Csupout1 Csupout2 Csupout3 Csupout4: library part "Cap Semi", "Capacitor (Semiconductor SIM Model)"
C_A C_REG: library part CMP-2006-04559-2, "Chip Capacitor, 1 uF, +/- 10%, 10 V, -55 to 85 degC, 0603 (1608 Metric), RoHS, Tape and Reel", Capacitance=1µF, Case Size/Dimension=0603, Dielectric=X5R, Manufacturer=AVX, Package Description="2-Pin Surface Mount Device, Body 1.6 x 0.81 mm", Rated Voltage=10V, Tolerance (%)=±10%
C_AFB: library part CMP-2006-04374-1, Manufacturer="AVX Interconnect / Elco"
Cf+ Cf-: library part CMP-2006-04007-1, Manufacturer="AVX Interconnect / Elco"
Csupin5 Csupout5: library part CMP-2006-04567-1, Manufacturer="AVX Interconnect / Elco"
Csw0 Csw1 Csw2 Csw3 Csw4: library part Cap, "Capacitor"
D1 D2 D3 D11 D22 D33: library part CMP-2000-04932-2, "Fast Switching Diode, 100 V, 0.15 A, -65 to 150 degC, 2-Pin?SOD123, RoHS, Tape and Reel", If - Forward Current=0.15A, Ir - Reverse Current=1uA, Manufacturer=DiodesIncorporated, Max Surge Current=2A, Maximum Operating Temperature=+150C, Minimum Operating Temperature=-65C, Operating Temperature Range=-65Cto+150C, Package / Case=SOD-123, Package Reference=SOD123-2, Peak Reverse Voltage=100V, Vf - Forward Voltage=1.25V
J1 J2: library part CMP-2000-05487-1, "SMA Right-Angle PCB Jack Receptacle, Brass Body, Gold Plated, 50 Ohm, 5-Pin THD, RoHS, Tray", Manufacturer=Molex, Package Description="5-Pin Through Hole Device, Body 14.8 x 6.35 mm, Pitch 2.54 mm"
J_supply U2 U_2V5 U_-2V5: "No Description Available"
LED_1M LED_10K LED_10M LED_100K LED_100M: library part CMP-1426-00005-1, "SMD mono-color Chip LED, WL-SMCW, Yellow", Color=Yellow, Manufacturer="Wuerth Elektronik"
LED_ON: library part CMP-2000-05654-1, "Single Color LED, 2 V, -30 to 85 degC, 2-Pin SMD (0603), RoHS, Tape and Reel", Emitting Color=YellowGreen, Forward Current=25mA, Forward Voltage=2.4V, Manufacturer=Dialight, Operating Temp Range=-40Cto100C, Operating Temperature Classification=Industrial, Package Description="2-Pin Surface Mount Device, Body 1.6 x 0.8 mm", Package Reference=0603, Package Type=SMD, Power Dissipation=60W, Reverse Voltage=5V, Test Current (It)=20mA
R1 R2 R5 R6 R7 R8 R9 R10 R11 R12 R13 R14 R_hyst R_LED0 R_LED1 R_LED2 R_LED3 R_LED4 R_LED_ON Rf2+ Rf2- Rf+ Rf- Rg1+ Rg1- Rg2+ Rg2- Rmatch+ Rmatch-: library part Res3, "Resistor"
R_J0: library part CMP-2005-01987-1, Manufacturer="Vishay Dale"
R_J1 R_J2 R_J3 R_J4 R_J5 R_J6 R_J9 R_J10 R_J11 R_J12 R_J13 R_J14 R_J15 R_J16 R_J17 R_J18 R_J19 R_J20 R_J21 R_J22 R_J23 R_J24 R_J25 R_J26: library part CMP-07231-004348-1, "Thick Film Chip Resistors 0805 0Ω 0.125W 5%", Case Code (Imperial)=0805, Case Code (Metric)=2012, Max Operating Temperature=155°C, Max Power Dissipation=125mW, Min Operating Temperature=-55°C, Package Quantity=5000, Resistance=0mR, Temperature Coefficient=500ppm/°C, Tolerance=5%, Voltage Rating=150V
RPG: library part CMP-2000-00182-1, Manufacturer=Panasonic
SW_1M SW_10k SW_10M SW_100K SW_100M: library part CMP-011-00006-1, "Slide Switch, SPDT, 500 V, -20 to 70 degC, 3-Pin THD, RoHS, Bulk", Contact Current Rating=200mA, Current Rating=2dA, Manufacturer=E-Switch, Max Operating Temperature=70°C, Min Operating Temperature=-20°C, Operating Force=250gf, Package Description="3-Pin Through Hole Device, Body 11.6 x 4 mm, Pitch 2.5 mm", Package Quantity=1000, Voltage Rating (AC)=30V
U1: "Integrated Circuit", Manufacturer_Name="Analog Devices", Mouser2 Part Number=584-LTC6419IVPBF
U3 U4 U5 U6 U7 U8 U9 U10 U11 U12: library part CMP-0790-00013-1, "2.1 Ohm On Resistance, +/-15 V / +12 V / +/-5 V iCMOS Dual SPST Switch, -40 to 125 degC, 10-pin SON (CP-10-9), Reel", Manufacturer="Analog Devices", Power Dissipation=1.8mW
U13: library part CMP-1633-00060-2, "CMOS 8-Bit Priority Encoder, D0016A, TUBE", F @ Nom Voltage(Max)(Mhz)=8, Generic Part Number=CD4532B, ICC @ Nom Voltage(Max)(mA)=0.3, Manufacturer="Texas Instruments", Operating Temperature Range(C)="-55 to 125", Rating=Catalog, tpd @ Nom Voltage(Max)(ns)=110, Voltage(Nom)(V)=5,10,15
U14: "No Description Available", Number_devices_in_Package=1
U_3V3: library part UA78M33IKVURG3, "No Description Available", Manufacturer="Texas Instruments"
U_5V U_-5V: "No Description Available", Manufacturer="Texas Instruments"

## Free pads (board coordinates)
  round 60 hole 78: 3(98.43,98.43) 3(98.43,2854.33) 3(3838.58,98.43) 3(3838.58,2854.33)

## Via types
v1: diameter 33.46, hole 19.68, Top Layer to Bottom Layer, 215 vias
v2: diameter 37/37 (per signal layer), hole 19.7, Top Layer to Bottom Layer, 16 vias
v3: diameter 33.47, hole 19.69, Top Layer to Bottom Layer, 4 vias
v4: diameter 37, hole 19.7, Top Layer to Bottom Layer, 4 vias

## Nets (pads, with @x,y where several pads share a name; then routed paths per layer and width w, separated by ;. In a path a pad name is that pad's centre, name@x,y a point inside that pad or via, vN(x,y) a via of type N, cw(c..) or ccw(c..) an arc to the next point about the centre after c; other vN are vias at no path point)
3V3: C2_supU2.2 C22_supU2.2 C_enU13.1 C_enU14.1 C_supU13.1 C_supU14.1 Csupout3.2 D3.1 D33.2 R_LED_ON.2 SW_1M.3 SW_10k.3 SW_10M.3 SW_100K.3 SW_100M.3 U2.8 U13.5 U13.14 U13.16 U14.6 U14.16 U_3V3.3 | length 9315.7
  Top Layer w12: R_LED_ON.2@419.46,594.41 419.73,594.69 v1(448.9,594.69) ; v1(1961.99,692.81) 1961.99,662.45 1981.01,643.42 U14.16@1981.01,575.22 ; U14.6@2108.96,344.72 2108.96,253.79 C_enU14.1@2109.39,253.37 ; C_supU13.1@2712.62,576.22 C_supU13.1@2715.6,579.2 ; C_enU13.1@2713.14,476.22 C_enU13.1@2715.78,473.57 ; 3264.48,2280.23 D3.1@3264.48,2321.78 ; U_3V3.3@3381.56,2301.6 U_3V3.3@3414.06,2301.6 ; D33.2@3405.97,2187.98 3369.08,2187.98 3369.08,2177.08 Csupout3.2@3466.86,2079.3 ; U2.8@3406.39,1511.74 3471.34,1511.74 3490.71,1531.11 3553.11,1531.11 C22_supU2.2@3554.09,1532.1 ; C22_supU2.2@3560.01,1532.1 3560.4,1531.71 3562.62,1533.94 v1(3586.81,1533.94)
  Top Layer w15: C_enU14.1@2109.39,253.37 2109.39,224.86 2136.06,198.18 2205.95,198.18 2383.99,376.22 U13.5@2410.36,376.22 2482.45,376.22 2582.45,476.22 U13.14@2632.8,476.22 C_enU13.1@2713.14,476.22 ; U13.16@2632.8,576.22 C_supU13.1@2712.62,576.22 ; C_supU13.1@2715.6,579.2 2717.04,577.76 v1(2717.04,545.09) ; C_enU13.1@2715.78,473.57 2715.91,473.7 2716.13,473.92 2716.47,474.27 2717.25,475.04 v1(2717.25,506.13)
  Bottom Layer w12: v1(448.9,594.69) 448.9,601.36 540.35,692.81 v1(1961.99,692.81) 1965.27,689.53 2652.67,689.53 2698.88,735.74 ; v1(2717.04,545.09) 2717.04,550.37 2715.78,551.63 2715.78,545.09 2715.78,526.68 ; v1(2717.25,506.13) 2717.25,525.22 2716.47,525.99 2716.13,526.33 2715.91,526.56 2715.78,526.68 ; SW_10k.3@2931.03,641.88 3032.56,743.42 3032.56,920.56 3144.42,1032.42 ; SW_1M.3@3138.72,641.88 3138.72,826.44 3346.41,1034.12 ; SW_100M.3@3346.41,641.88 3346.41,1034.12 ; v1(3433.13,2077.82) 3434,2077.82 3586.81,1925.01 3586.81,1602.87 v1(3586.81,1533.94) 3822.75,1533.94 3824.97,1531.71 3878.92,1477.77 3878.92,1123.01 3790.03,1034.12 3439.09,1034.12 ; SW_10M.3@3554.1,641.88 3554.1,826.43 3346.41,1034.12 ; SW_100K.3@3769.21,641.58 3769.21,704 3639.99,833.22 3623.22,850 3439.09,1034.12 ; 2698.88,735.74 2834.66,599.96 2834.66,555.8 2805.54,526.68 2715.78,526.68 ; 2698.88,735.74 2995.56,1032.42 3144.42,1032.42 ; 3144.42,1032.42 3146.13,1034.12 3346.41,1034.12 ; 3346.41,1034.12 3439.09,1034.12
+2V5: C1_supU1.1 C3_supU1.1 C11_supU1.1 C33_supU1.1 Csupout4.2 R_J0.1 RPG.2 U1.12 U1.15 U_2V5.1 U_2V5.2 | length 5922
  Top Layer w7.87: C11_supU1.1@699.25,1548.67 707.21,1540.72 799.51,1540.72 844.26,1495.96 U1.15@844.26,1474.34 ; U1.12@903.32,1474.34 903.32,1500.46 934.64,1531.78 992.25,1531.78 C33_supU1.1@1027.86,1567.39 ; Csupout4.2@2935.8,2710.97 2936.44,2710.33 2937.11,2709.66 2935.9,2708.45 v1(2935.9,2684.2) ; 2952,2552.49 RPG.2@2990.38,2552.49
  Top Layer w15: 699.16,1687.6 699.25,1687.51 ; R_J0.1@897.32,1024.89 R_J0.1@903.45,1018.76 ; C33_supU1.1@1027.86,1567.39 C3_supU1.1@1084.64,1567.39
  Top Layer w20: C11_supU1.1@699.25,1548.67 699.25,1605.77 699.25,1687.51 ; R_J0.1@897.32,1024.89 156.22,1024.89 56.55,1124.55 56.55,1485.22 258.92,1687.6 699.16,1687.6 987.94,1976.37 ; C3_supU1.1@1084.96,1567.71 1108.9,1567.71 1118.58,1577.39 1118.58,1735.75 987.94,1866.39 987.94,1976.37 ; v1(2315.85,2124.25) 2313.79,2126.32 1379.02,2126.32 1229.08,1976.37 987.94,1976.37
  Bottom Layer w20: v1(2315.85,2124.25) 2448.3,2256.71 2797.21,2256.71 2854.33,2313.82 2854.33,2609.82 2928.71,2684.2 v1(2935.9,2684.2)
+5V: C1_supU2.2 C11_supU2.2 Csupin3.2 Csupin4.2 Csupout1.2 D1.1 D3.2 D11.2 U2.1 U2.4 U_2V5.5 U_2V5.8 U_3V3.1 U_5V.3 | length 2506.9
  Top Layer w7.87: C11_supU2.2@3080.12,1516.74 C11_supU2.2@3083.32,1513.54 ; v1(3154.09,1420.13) 3183.82,1420.13 3198.66,1434.97 U2.4@3229.95,1434.97
  Top Layer w10: Csupin4.2@3181.39,2710.97 Csupin4.2@3181.39,2719.83
  Top Layer w12: v1(3054.83,1519.27) 3054.83,1519.17 3057.26,1516.74 C11_supU2.2@3080.12,1516.74 ; C11_supU2.2@3083.32,1513.54 C1_supU2.2@3139.33,1513.54 ; C1_supU2.2@3142.05,1510.82 U2.1@3230.06,1510.82
  Top Layer w20: D1.1@2471.09,2345.71 2542.56,2345.71 ; U_5V.3@2502.56,2434 U_5V.3@2502.56,2466.5 ; 2637.99,2417.89 2659.96,2439.87 D11.2@2659.96,2467.33 ; Csupout1.2@2758,2519.15 2758.34,2518.81 2758.34,2484.53 v1(2758.34,2483.13) 2758.34,2483.47 2757.81,2484 2758.32,2484.5 2757.4,2485.42 2762.61,2490.62 2763.52,2489.71 3177.07,2076.15 v1(3177.07,2013.77) ; D3.2@3264.48,2445.8 3264.48,2486.94 ; 3321.87,2481.6 U_3V3.1@3414.06,2481.6 ; 3360.26,2615.42 Csupin3.2@3468.3,2615.42
  Bottom Layer w20: v1(3054.83,1519.27) 3050.37,1523.73 3050.37,1623.12 3074.42,1647.17 3177.96,1647.17 ; v1(3154.09,1420.13) 3154.09,1388.99 3186.48,1356.6 3276.25,1356.6 3318.68,1399.03 3318.68,1506.45 3177.96,1647.17 ; 3177.07,1648.79 v1(3177.07,2013.77) ; 3178.69,1647.17 3177.96,1647.17
+15V: C1_U4.2 C1_U8.2 C15_1.2 C15_2.2 Csupin1.2 D1.2 J_supply.1 R_J1.1 R_J3.1 R_J5.1 R_J9.1 R_J11.2 R_J12.2 R_J13.2 R_J14.2 U4.5 U8.5 U_5V.1 | length 9866.5
  Top Layer w12: C1_U4.2@1430.8,883.15 1445.3,883.15 1470.05,907.9 U4.5@1490.85,907.9 ; U8.5@2646.2,2007.28 2663.99,2025.07 C1_U8.2@2703.02,2025.07
  Top Layer w15: v1(295.28,1771.65) 420.21,1896.59 v1(791.99,1896.59) ; v1(1225.61,1406.05) 1231.84,1399.83 R_J9.1@1269.38,1399.83 ; v1(1226.77,1167.37) 1266.53,1167.37 1267.93,1165.96 R_J5.1@1269.34,1167.36 ; R_J3.1@1269.38,1645.04 1269.38,1678.71 1152.25,1795.84 v1(1152.25,1898.85) 1183.88,1930.48 v1(1264.05,1930.48) 1264.05,1893.16 R_J1.1@1269.38,1887.84 ; v1(1392.17,883.53) 1403,883.53 1403.06,883.59 1403.5,883.15 C1_U4.2@1430.8,883.15 ; C15_1.2@1538.93,2231.11 1580.27,2231.11 1627.66,2183.72 2743.77,2183.72 2902.23,2025.25 ; 2168.18,2463.46 Csupin1.2@2168.18,2523.61 ; 2280.27,2345.71 D1.2@2347.08,2345.71 ; 2322.56,2383.03 U_5V.1@2322.56,2466.5 ; C1_U8.2@2703.02,2025.07 2703.21,2025.25 2902.23,2025.25 ; R_J11.2@2910.21,1085.56 2905.52,1090.25 R_J13.2@2905.52,1334.9 2947.32,1334.9 3095.11,1187.12 3812.5,1187.12 3848.37,1222.99 3848.37,1482.24 3673.17,1657.44 2998.78,1657.44 2927.69,1586.35 R_J14.2@2906.95,1586.35 2912.08,1591.48 2912.08,1789.19 R_J12.2@2902.23,1789.19 2902.23,2024.38 2903.11,2024.38 2902.23,2025.25
  Bottom Layer w15: v1(295.28,1771.65) 34.81,1511.18 34.81,1417.64 34.81,1146.3 342.22,838.89 1357.42,838.89 1396.25,877.71 1392.17,881.79 v1(1392.17,883.53) ; v1(791.99,1896.59) 804.06,1896.59 806.32,1898.85 v1(1152.25,1898.85) ; v1(1225.61,1406.05) 1225.61,1173.47 1230.73,1168.35 1230.66,1168.29 1229.02,1166.65 1227.61,1168.05 1227.46,1168.05 v1(1226.77,1167.37) 1225.22,1165.82 1227.4,1163.64 1227.4,970.67 1312.12,885.95 v1@1397.51,885.95 ; v1(1264.05,1930.48) 1266.89,1930.48 1567.89,2231.49 v1(1582.98,2231.49)
-2V5: C2_supU1.1 C4_supU1.1 C22_supU1.1 C44_supU1.1 Csupout5.2 U1.13 U1.14 U1.21 U1.22 U1.23 U1.24 U_-2V5.1 U_-2V5.2 | length 2387.3
  Top Layer w7.87: C22_supU1.1@829.12,1565.75 863.77,1531.1 863.77,1474.52 U1.14@863.95,1474.34 ; U1.13@883.63,1474.34 883.63,1562.46 C44_supU1.1@890.02,1568.85
  Top Layer w10: U_-2V5.2@212.99,2268.3 159.98,2268.3 140.3,2287.98 U_-2V5.1@212.99,2287.98
  Top Layer w20: v1(745.17,1567.29) 745.33,1567.13 827.74,1567.13 C22_supU1.1@829.12,1565.75 ; U1.21@845.72,1401.03 846.07,1401.39 v3(846.07,1418.53) ; v3@845.72,1418.53 U1.22@845.72,1437.45 ; C44_supU1.1@890.02,1568.85 890.99,1567.87 976.92,1567.87 v1(978.6,1566.19) ; U1.23@901.86,1401.03 902.91,1402.08 v3(902.91,1419.62) 901.86,1420.67 U1.24@901.86,1437.45
  Bottom Layer w20: v1(140.98,2264.32) 132.94,2264.32 132.39,2264.86 106.72,2239.19 106.72,2074.01 408.04,1772.69 898.43,1772.69 978.6,1692.53 v1(978.6,1566.19) 977.5,1567.29 v1(745.17,1567.29) 745.17,1547.84 860.28,1432.73
-5V: Csupin5.2 Csupout2.1 D2.1 D22.1 U_-2V5.5 U_-2V5.8 U_-2V5.9 U_-5V.3 | length 47.9
  Top Layer w20: Csupout2.1@328.31,2413.69 328.31,2389.46 329.7,2388.06 ; 424.46,2385.94 D22.1@424.46,2407.59
-15V: C2_U4.2 C2_U8.2 C15_3.1 C15_4.1 Csupin2.2 D2.2 J_supply.3 R_J2.1 R_J4.1 R_J6.1 R_J10.1 U4.8 U8.8 U_-5V.2 | length 7133.4
  Top Layer w7.87: C2_U4.2@1661.52,932.17 1662.79,930.9 1664.19,932.3 1692.04,932.3 1692.04,932.36 1692.09,932.4 1692.09,934.67 1694.07,932.68 v1(1695.13,932.68)
  Top Layer w12: U4.8@1608.96,947.27 1647.5,947.27 C2_U4.2@1662.06,932.71 ; C2_U8.2@2478.86,1981.89 2492.84,1967.91 U8.8@2528.09,1967.91
  Top Layer w15: Csupin2.2@687.73,2684.58 760.31,2684.58 ; v1(1232.01,1566.33) 1264.81,1566.33 1266.16,1567.68 R_J4.1@1269.38,1564.46 ; v1(1232.1,1810.91) 1240.35,1810.91 1242.32,1808.94 1242.8,1808.46 R_J2.1@1269.38,1808.46 ; v1(1269.96,786.05) 1269.96,1087.99 R_J6.1@1269.38,1088.58 1243.46,1088.58 1196.46,1135.58 1196.46,1207.47 1269.38,1280.38 R_J10.1@1269.38,1318.95 1222.42,1318.95 1171.13,1267.66 1171.13,1091.73 1030.81,951.41 171.45,951.41 24.24,1098.61 24.24,1617.8 444.13,2037.68 1113.76,2037.68 1300.32,2224.24 1295.94,2228.61 1295.28,2229.28 1295.08,2229.08 v1(1292.14,2229.08) ; v1@1308.34,2232.26 C15_3.1@1321.09,2219.51 ; C15_3.1@1330.73,2231.11 1405.95,2155.89 2380.81,2155.89 2416.36,2120.35 2416.36,2009.46 2443.92,1981.89 C2_U8.2@2478.86,1981.89
  Bottom Layer w12: v1@1230.41,1810.88 v1@1231.17,1810.11
  Bottom Layer w15: v1@1230.41,1810.88 1213.11,1828.17 1213.11,2100.33 1293.99,2181.21 1293.99,2227.23 v1(1292.14,2229.08) ; v1@1231.17,1810.11 1231.3,1809.99 1232.1,1810.79 v1(1232.1,1810.91) 1232.1,1799.77 1231.8,1799.47 1231.8,1566.54 v1(1232.01,1566.33) ; v1(1269.96,786.05) 1269.96,787.44 1667.37,787.44 1695.55,815.62 1695.55,928.79 1692.04,932.3 1692.04,932.36 1692.09,932.4 1692.09,934.67 1694.07,932.68 v1(1695.13,932.68)
Diff_pair0_N: C2-.2 Rg2-.2 | length 1055
  Top Layer w9.84: C2-.2@446.08,1536.13 446.08,1509.94 478.75,1477.27 478.75,1160.35 541.97,1097.13 989.62,1097.13 1026.48,1133.99 Rg2-.2@1026.48,1210.46
Diff_pair00_N: C2-.1 U1.16 | length 303.4
  Top Layer w9.84: C2-.1@557.89,1536.13 584.02,1510 807.92,1510 824.58,1493.34 U1.16@824.58,1474.34
Diff_pair0_P: C2+.2 Rg2+.2 | length 984.3
  Top Layer w9.84: C2+.2@434.49,1392.88 455.63,1371.75 455.63,1155.64 528.05,1083.22 533.81,1077.45 997.78,1077.45 1003.54,1083.22 1046.16,1125.83 1046.16,1173.71 Rg2+.2@1079.74,1207.29
Diff_pair00_P: C2+.1 U1.17 | length 272.8
  Top Layer w9.84: C2+.1@551.43,1387.75 612.43,1448.75 U1.17@798.99,1448.75
Diff_pair1_N: U1.10 U3.1 U4.2 U5.2 U6.1 U7.2 | length 2279.1
  Top Layer w9.84: U1.10@948.59,1448.75 970.95,1448.75 1008.48,1486.28 1268.55,1486.28 v1(1288.23,1466.59) ; v1(1296.19,1245.71) v1@1296.69,1245.71 ; v1@1301.03,1469.45 U7.2@1488.28,1469.45 ; U5.2@1488.28,1709.48 1313.39,1709.48 1300.27,1722.61 1297.8,1722.61 v1(1297.49,1722.92) 1301.55,1722.92 1301.55,1723.89 1302.84,1725.18 1302.84,1917.56 1354.25,1968.97 U3.1@1488.28,1968.97 ; U6.1@1490.59,1250.8 1301.77,1250.8 v1@1296.69,1245.71 ; U4.2@1490.85,966.96 1376.67,966.96 1304.29,1039.34 1304.29,1238.11 1300.16,1242.24 v1@1296.69,1245.71
  Bottom Layer w9.84: v1@1286.76,1478.4 1277.64,1487.52 1277.64,1512.39 1305.37,1540.11 1305.37,1715.04 v1(1297.49,1722.92) ; v1(1288.23,1466.59) 1304.06,1450.76 1304.06,1253.59 v1@1300.3,1249.83 ; v1@1300.64,1251.38 1300.3,1251.04 v1@1300.3,1249.83 ; v1@1300.3,1249.83 v1(1296.19,1245.71) 1300.3,1245.71 v1@1300.3,1249.83
Diff_pair1_P: U1.11 U3.2 U4.1 U5.1 U6.2 U7.1 | length 2200.1
  Top Layer w9.84: U1.11@923.23,1474.34 U1.11@923,1474.34 923,1490.76 938.21,1505.96 1298.17,1505.96 v1@1304.18,1499.95 ; v1(1305.97,1501.74) v1@1304.18,1499.95 ; v1@1326.91,1216.49 v1(1332.68,1222.25) 1341.54,1231.11 U6.2@1490.59,1231.11 ; v1@1329.31,1214.09 1323.97,1208.75 1323.97,1047.49 1384.82,986.64 U4.1@1490.85,986.64 ; v1@1330.09,1748.86 1349.78,1729.17 U5.1@1488.28,1729.17 ; v1@1331.47,1750.26 1323.55,1758.19 1323.55,1910.43 1362.4,1949.29 U3.2@1488.28,1949.29 ; U7.1@1488.28,1489.14 1315,1489.14 v1@1304.18,1499.95
  Bottom Layer w9.84: v1(1305.97,1501.74) v1@1304.18,1499.95 ; v1(1331.49,1750.28) 1328.73,1750.28 1323.65,1745.2 1325.05,1743.8 1325.05,1531.96 1298.61,1505.52 v1@1304.18,1499.95 ; v1(1332.68,1222.25) 1323.75,1231.18 1323.75,1480.39 v1@1304.18,1499.95
Diff_pair2_N: R5.2 U3.10 | length 302.2
  Top Layer w9.84: U3.10@1606.39,1968.97 1898.27,1968.97 R5.2@1905.6,1976.3
Diff_pair2_P: R6.2 U3.9 | length 312.4
  Top Layer w9.84: U3.9@1606.39,1949.29 1874.71,1949.29 R6.2@1905.89,1918.11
